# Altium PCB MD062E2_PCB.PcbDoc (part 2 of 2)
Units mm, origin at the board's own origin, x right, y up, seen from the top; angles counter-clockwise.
Board outline 85.34 x 64.01 mm, 4 copper layers (Top Layer, Signal Layer 1, Signal Layer 2, Bottom Layer), stack 1.565 mm thick; 172 components, 94 nets, 455 pads, 231 vias.
Unrouted connection lines stored in the file: 2.
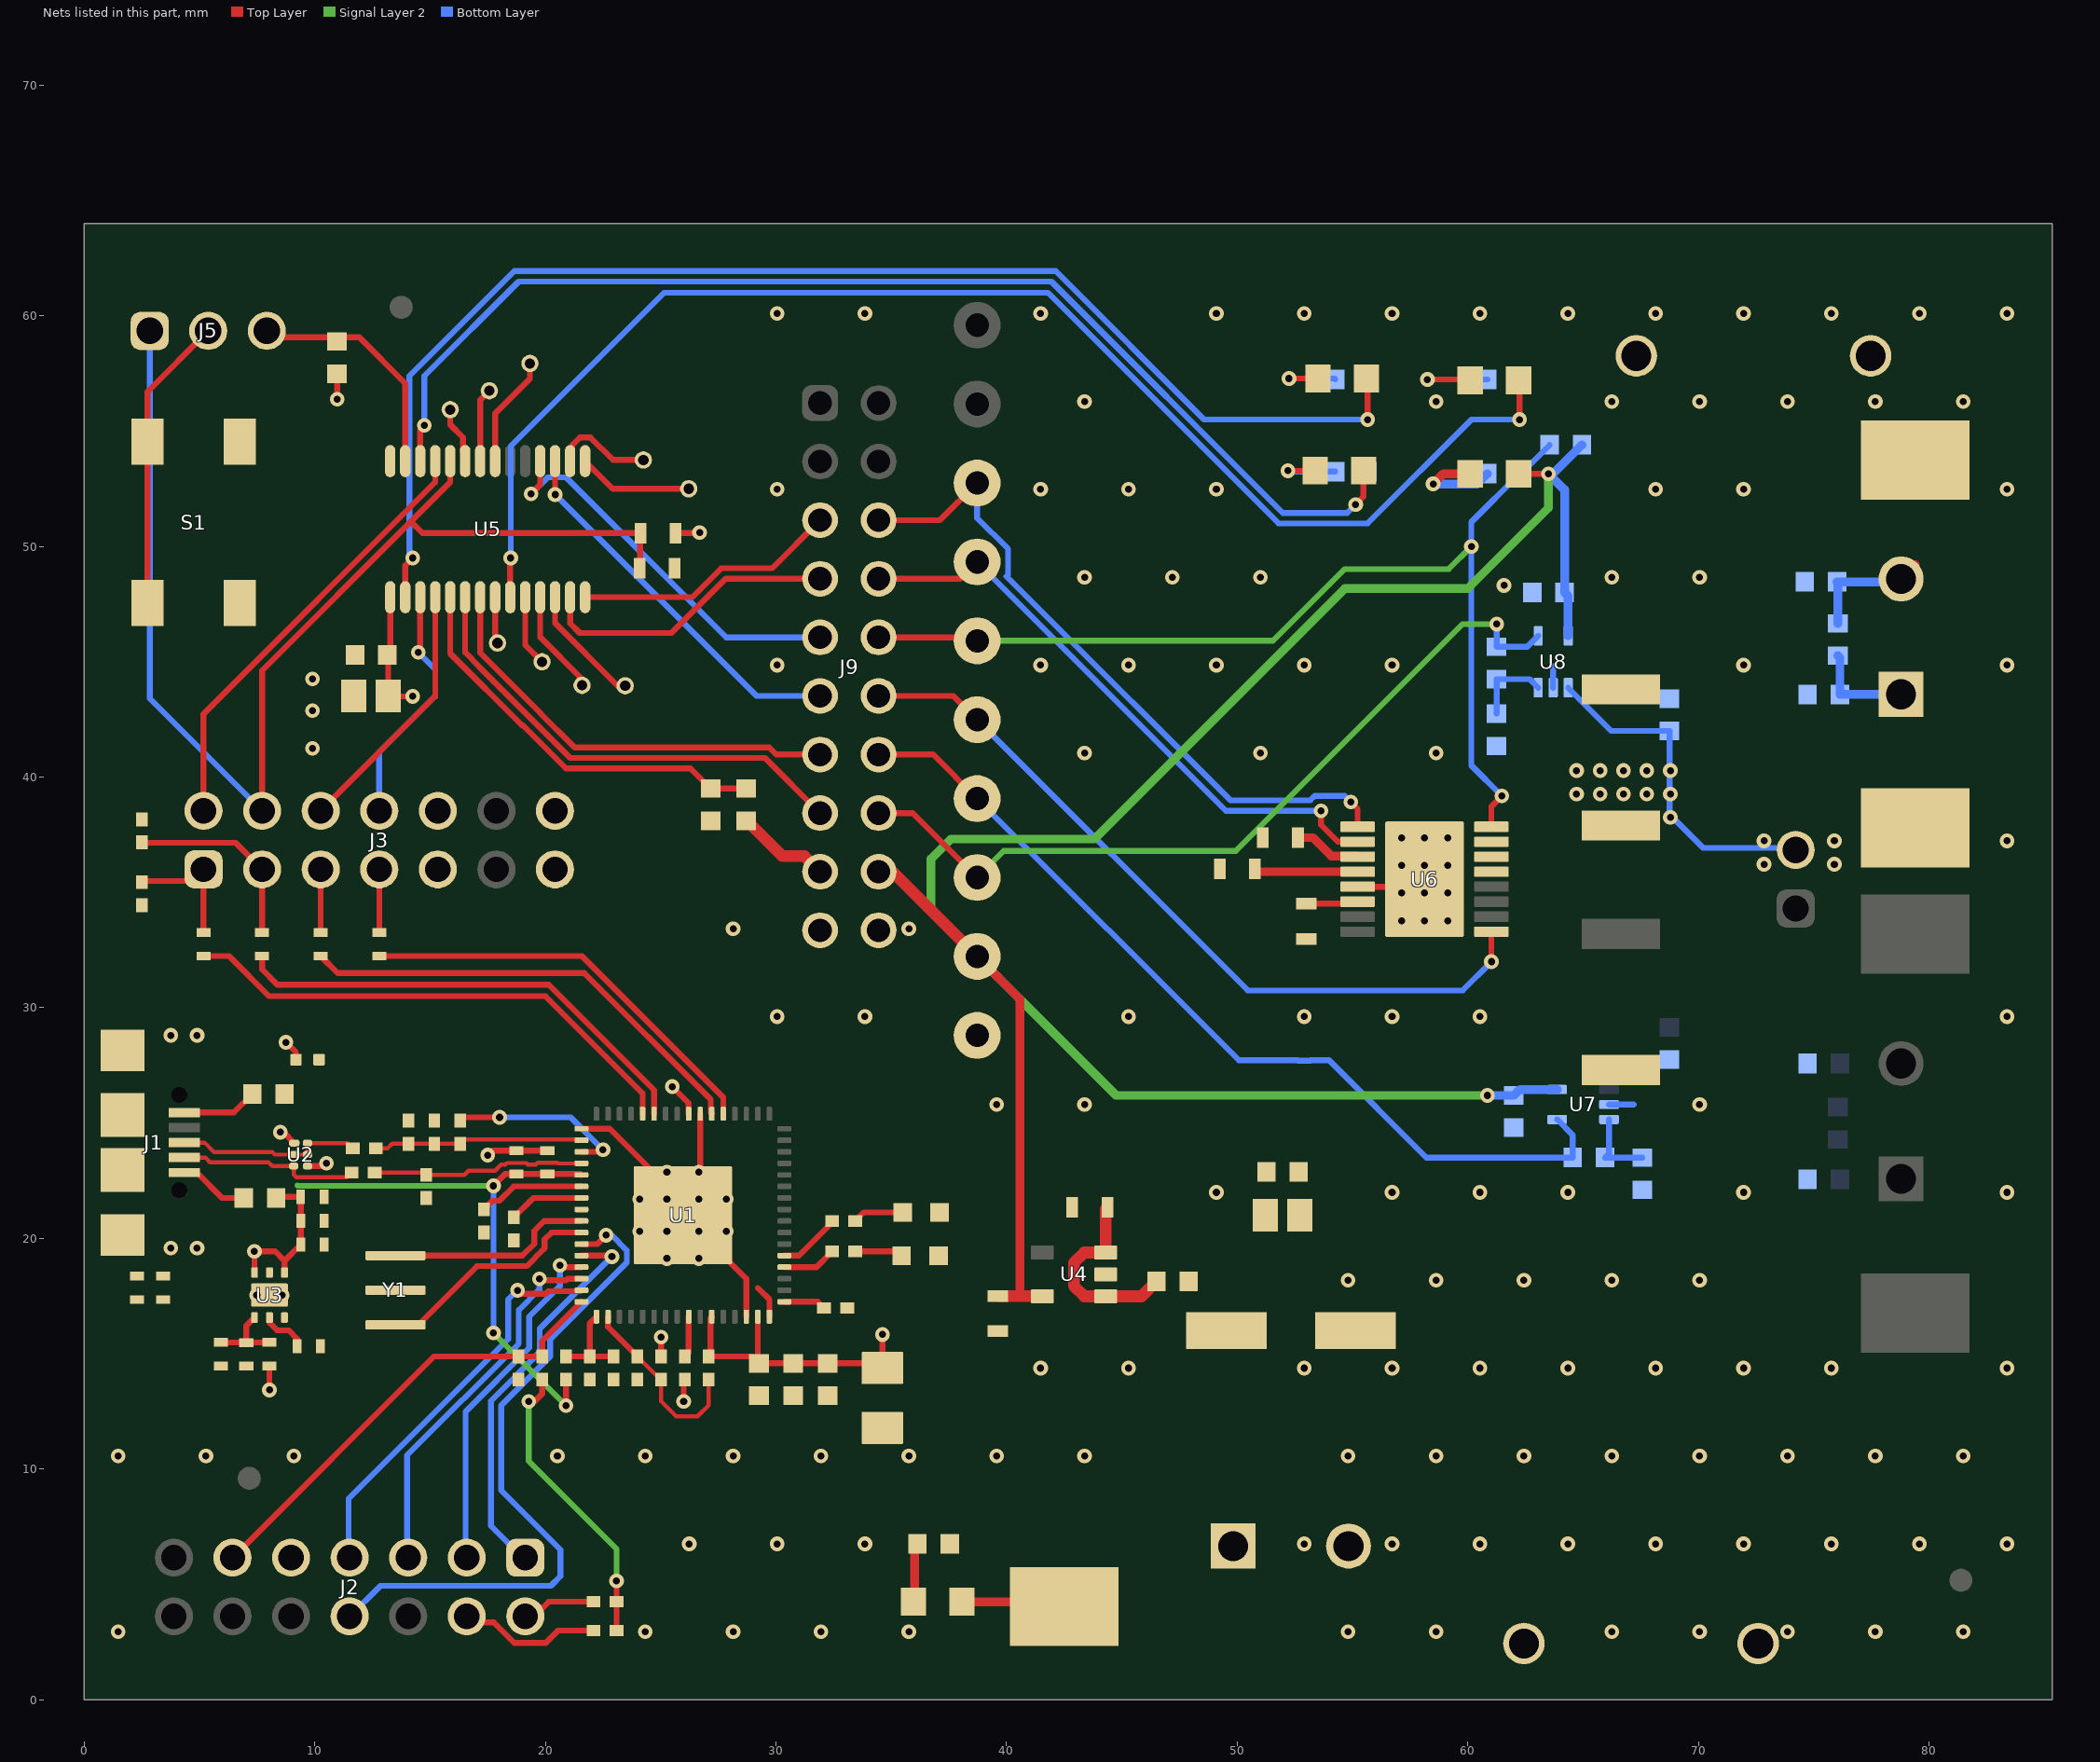
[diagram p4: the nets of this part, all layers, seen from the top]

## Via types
v1: diameter 0.635/0.635/0.635/0.635 (per signal layer), hole 0.305, Top Layer to Bottom Layer, tented both sides, 231 vias

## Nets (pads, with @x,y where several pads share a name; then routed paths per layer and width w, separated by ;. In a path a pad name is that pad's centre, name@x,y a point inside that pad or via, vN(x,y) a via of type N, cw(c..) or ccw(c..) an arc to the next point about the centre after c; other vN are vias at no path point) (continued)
BIN1: J9.6 TP19.1 U6.9 | length 29.9
  Top Layer w0.254: J9.6@34.452,51.139 37.112,51.139 TP19.1@38.725,52.752 ; v1(54.929,38.92) 55.224,38.625 U6.9@55.224,37.849
  Bottom Layer w0.254: TP19.1@38.725,52.752 38.725,51.23 40.068,49.887 40.068,48.774 39.996,48.702 41.127,47.571 49.704,38.994 53.173,38.994 53.363,39.185 54.664,39.185 v1(54.929,38.92)
BIN1_MCU: J9.5 U5.14 | length 11.6
  Top Layer w0.254: U5.14@21.725,47.8 26.378,47.8 27.631,49.053 29.826,49.053 J9.5@31.912,51.139
BIN2: J9.8 TP20.1 U6.10 | length 26.5
  Top Layer w0.254: J9.8@34.452,48.599 37.993,48.599 TP20.1@38.725,49.331 ; v1(53.63,38.54) 53.63,37.934 54.365,37.199 U6.10@55.224,37.199
  Bottom Layer w0.254: TP20.1@38.725,49.331 49.516,38.54 v1(53.63,38.54)
BIN2_MCU: J9.7 U5.13 | length 13.1
  Top Layer w0.254: U5.13@21.075,47.8 21.075,46.665 21.494,46.246 25.466,46.246 27.819,48.599 J9.7@31.912,48.599
BISEN: C35.1 J7.2 R24.2 U6.6 U8.1 | length 14.9
  Bottom Layer w0.254: U8.1@64.353,43.875 66.228,42 C35.1@68.75,42 68.75,38.387 70.206,36.932 J7.2@74.219,36.932
  other v1: 72.847,36.22 75.895,36.22 72.847,37.236 75.895,37.236 68.783,38.252 64.719,39.268 65.735,39.268 66.751,39.268 67.767,39.268 68.783,39.268 64.719,40.284 65.735,40.284 66.751,40.284 67.767,40.284 68.783,40.284
BOUT1: C38.2 C39.1 J11.2 TP16.1 U6.7 | length 6.9
  Top Layer w0.381: J11.2@78.791,48.592 J11.2@79.4,49.201 ; TP16.1@79.4,52.327 TP16.1@79.4,53.75
  Bottom Layer w0.381: C38.2@76.048,46.663 76.048,48.43 C39.1@76.014,48.463 78.662,48.463 J11.2@78.791,48.592
BOUT2: C38.1 C41.1 J11.1 TP15.1 U6.5 | length 5.8
  Top Layer w0.381: TP15.1@79.4,37.795 TP15.1@79.4,39.218
  Bottom Layer w0.381: C38.1@76.048,45.263 76.138,45.172 C41.1@76.138,43.586 78.785,43.586 J11.1@78.791,43.592
DEV_ID: R21.1 R22.2 U5.5 | length 17.7
  Top Layer w0.254: U5.5@15.875,47.8 15.875,45.36 19.005,42.23 19.041,42.23 20.895,40.376 26.296,40.376 R22.2@27.164,39.509 R21.1@28.717,39.509
EZFET_AVBUS: C18.1 R14.1 R15.2 U1.1 | length 3.9
  Top Layer w0.254: R14.1@20.9,14.885 C18.1@21.931,14.885 ; U1.1@22.217,16.605 21.931,16.319 C18.1@21.931,14.885 ; R15.2@22.962,14.885 C18.1@21.931,14.885
EZFET_AVCC2ADC: C19.1 R16.1 R17.2 U1.2 | length 8.3
  Top Layer w0.178: C19.1@23.994,14.885 24.994,13.885 R17.2@25.025,13.885 25.025,12.931 25.672,12.285 26.596,12.285 27.087,12.776 R16.1@27.087,13.885
  Top Layer w0.254: U1.2@22.717,16.605 22.717,16.162 C19.1@23.994,14.885
EZFET_D_N: C11.1 R4.2 U1.52 | length 9.3
  Top Layer w0.178: R4.2@12.6,22.86 14.732,22.86 C11.1@14.837,22.755 16.492,22.755 16.677,22.94 17.822,22.94 18.088,23.206 18.262,23.206 18.326,23.27 19.174,23.27 19.238,23.206 19.593,23.206 19.663,23.276 20.512,23.276 20.538,23.25 21.562,23.25 U1.52@21.567,23.255
EZFET_D_P: C12.1 R5.2 R6.2 R7.1 U1.50 | length 9.1
  Top Layer w0.178: R5.2@12.65,23.9 13.15,23.9 13.355,24.105 R6.2@14.062,24.105 C12.1@15.187,24.105 R7.1@16.312,24.105 16.462,24.255 16.462,24.292 21.529,24.292 U1.50@21.567,24.255
EZFET_LED0: R1.2 U1.20 | length 2.4
  Top Layer w0.254: U1.20@30.367,18.755 31.757,18.755 R1.2@32.437,19.435
EZFET_LED1: R2.2 U1.21 | length 2.7
  Top Layer w0.254: U1.21@30.367,19.255 31,19.255 32.437,20.692 R2.2@32.437,20.75
EZFET_PUR: R7.2 U1.51 | length 7.8
  Top Layer w0.254: R7.2@16.312,25.105 16.458,25.25 v1(18.017,25.25) ; U1.51@21.567,23.755 22.406,23.755 v1(22.5,23.848)
  Bottom Layer w0.254: v1(18.017,25.25) 21.098,25.25 v1(22.5,23.848)
EZFET_RST: C24.1 J2.11 R19.1 U1.64 | length 20.2
  Top Layer w0.254: J2.11@6.385,6.09 15.18,14.885 C24.1@18.837,14.885 R19.1@19.869,14.885 19.869,15.557 U1.64@21.567,17.255
EZFET_TCK: J2.7 U1.63 | length 17.6
  Top Layer w0.254: v1(18.793,17.75) 18.937,17.605 20.017,17.605 20.12,17.709 21.521,17.709 U1.63@21.567,17.755
  Bottom Layer w0.254: J2.7@11.465,6.09 11.465,8.703 18.394,15.633 18.394,17.352 v1(18.793,17.75)
EZFET_TDI: J2.3 U1.61 | length 15.4
  Top Layer w0.254: v1(20.634,18.834) 20.713,18.755 U1.61@21.567,18.755
  Bottom Layer w0.254: J2.3@16.545,6.09 16.545,12.499 19.302,15.257 19.302,16.605 20.634,17.936 v1(20.634,18.834)
EZFET_TDO: J2.1 U1.60 | length 17.2
  Top Layer w0.254: U1.60@21.567,19.255 22.843,19.255 v1(22.887,19.211)
  Bottom Layer w0.254: J2.1@19.085,6.09 17.637,7.537 17.637,12.95 19.756,15.069 19.756,16.08 v1(22.887,19.211)
EZFET_TEST: J2.8 U1.59 | length 29.8
  Top Layer w0.254: U1.59@21.567,19.755 22.255,19.755 v1(22.639,20.139)
  Bottom Layer w0.254: J2.8@11.465,3.55 12.853,4.938 20.239,4.938 20.653,5.352 20.653,6.51 18.093,9.07 18.091,9.07 18.091,12.762 20.21,14.881 20.21,15.622 23.532,18.944 23.532,19.478 22.871,20.139 v1(22.639,20.139)
EZFET_TMS: J2.5 U1.62 | length 16.4
  Top Layer w0.254: v1(19.75,18.25) 19.81,18.189 20.901,18.189 20.961,18.25 21.562,18.25 U1.62@21.567,18.255
  Bottom Layer w0.254: J2.5@14.005,6.09 14.005,10.601 18.848,15.445 18.848,16.894 19.75,17.796 v1(19.75,18.25)
EZFET_UARTRXD: R10.1 U1.38 | length 20.1
  Top Layer w0.254: R10.1@10.258,32.242 11,31.5 21.692,31.5 27.171,26.021 27.171,25.451 U1.38@27.217,25.405
EZFET_UARTTXD: R11.1 U1.37 | length 18.2
  Top Layer w0.254: R11.1@12.803,32.242 21.592,32.242 27.717,26.117 U1.37@27.717,25.405
EZFET_USB_Shield: C5.1 J1.Shell R3.2
  other v1: 3.758,19.581 4.898,19.581 3.758,28.804 4.898,28.804
EZFET_V18: C2.1 U1.55 | length 3.3
  Top Layer w0.254: C2.1@18.637,20.913 19.479,21.755 U1.55@21.567,21.755
EZFET_VBUS: C9.2 C13.1 C14.1 C15.1 C23.1 C25.1 L1.2 R14.2 U1.53 U2.1 U3.4 U3.6 | length 33.3
  Top Layer w0.254: U3.6@7.387,18.52 7.387,19.431 v1(7.384,19.435) 8.279,19.435 8.687,19.027 ; L1.2@8.328,21.755 8.377,21.803 C13.1@9.387,21.803 9.395,21.795 C14.1@9.395,20.763 C15.1@9.395,19.735 8.687,19.027 ; v1(8.503,24.605) 8.642,24.605 U2.1@9.112,24.135 ; U3.4@8.687,18.52 8.687,19.027 ; v1(8.75,28.5) 9.187,28.063 C9.2@9.187,27.75 ; v1(17.75,22.28) 18.261,22.79 C25.1@18.75,22.79 20.081,22.79 C23.1@20.087,22.797 21.525,22.797 U1.53@21.567,22.755 ; v1(20.9,12.75) R14.2@20.9,13.885
  Signal Layer 2 w0.254: 9.25,22.3 9.271,22.28 v1(17.75,22.28) ; v1(17.75,15.9) v1(20.9,12.75)
  Bottom Layer w0.254: v1(17.75,15.9) v1(17.75,22.28)
EZFET_VCC: C6.1 C7.1 C8.1 C10.1 J3.9 R12.1 R13.1 R16.2 R18.2 R19.2 U1.11 U1.15 U1.40 | length 28.3
  Top Layer w0.254: v1(8.037,13.429) R18.2@8.037,14.477 ; v1(19.275,12.931) 19.533,12.931 19.869,13.267 R19.2@19.869,13.885 ; R12.1@23.087,3 R13.1@23.087,4.25 v1(23.087,5.148) ; v1(25.5,26.58) 26.217,25.863 U1.40@26.217,25.405 ; U1.11@27.217,16.605 27.164,16.552 27.164,14.961 R16.2@27.087,14.885 28.963,14.885 C7.1@29.217,14.631 ; U1.15@29.217,16.605 C7.1@29.217,14.631 ; v1(34.613,15.835) C6.1@34.613,14.385 34.413,14.585 C10.1@32.237,14.585 C8.1@30.75,14.585 C7.1@29.263,14.585 C7.1@29.217,14.631
  Signal Layer 2 w0.254: v1(19.275,12.931) 19.275,10.352 23.087,6.539 v1(23.087,5.148)
EZFET_VCORE: C3.1 U1.17 | length 1.8
  Top Layer w0.254: U1.17@30.367,17.255 31.817,17.255 C3.1@32.087,16.985
EZFET_VREF: C1.1 U1.9 | length 1.8
  Top Layer w0.254: C1.1@26.056,14.885 26.217,15.045 U1.9@26.217,16.605
EZFET_VUSB: C4.1 U1.54 | length 4.6
  Top Layer w0.254: C4.1@17.337,21.26 17.713,21.635 18.017,21.635 18.636,22.255 U1.54@21.567,22.255
EZFET_XT2IN: U1.57 Y1.1 | length 9
  Top Layer w0.254: Y1.1@13.5,19.255 19.005,19.255 19.519,19.769 19.519,20.33 19.944,20.755 U1.57@21.567,20.755
EZFET_XT2OUT: U1.58 Y1.3 | length 9.9
  Top Layer w0.254: Y1.3@13.5,16.255 14.491,16.255 17.037,18.801 19.193,18.801 19.906,19.513 ; 19.944,19.552 19.973,19.581 19.973,19.964 20.264,20.255 U1.58@21.567,20.255
GND: C1.2 C2.2 C3.2 C4.2 C5.2 C6.2 C7.2 C8.2 C9.1 C10.2 C11.2 C12.2 C13.2 C14.2 C15.2 C16.1 C17.1 C18.2 C19.2 C20.2 C21.2 C22.2 C23.2 C24.2 C25.2 C26.2 C27.2 C28.2 C29.2 C30.2 C31.2 C32.2 C33.2 C34.2 C35.2 C37.2 C39.2 C40.2 C41.2 C42.2 C43.2 C44.2 C46.2 D1.1 D2.1 J2.9 J3.13 J3.14 J4.2 J9.19 J9.20 L2.2 R3.1 R6.1 R15.1 R17.1 R22.1 R23.1 R24.1 R26.1 R27.1 R28.1 R29.1 R32.1 R33.1 S1.3 S1.4 TP7.1 TP7.2 TP8.1 TP8.2 TP26.1 U1.14 U1.16 U1.39 U1.49 U1.56 U1.65 U2.4 U3.3 U3.5 U3.7@8.037,17.545 U4.2 U5.28 U6.13 U6.17 U7.2 U8.2 Y1.2 | length 28.4
  Top Layer w0.254: U2.4@9.687,23.135 10.389,23.135 v1(10.509,23.255) ; v1(17.5,23.61) 17.697,23.806 C25.2@18.75,23.806 20.081,23.806 C23.2@20.087,23.813 ; U1.49@21.567,24.755 22.794,24.755 25.967,21.582 U1.65@25.967,21.005 ; R17.1@25.025,14.885 v1(25.025,15.718) ; v1(26,12.931) 26,13.828 C1.2@26.056,13.885 ; U1.39@26.717,25.405 26.717,21.755 v1(26.662,21.7) U1.65@25.967,21.005 ; U1.14@28.717,16.605 28.717,18.255 v1(26.662,20.31) U1.65@25.967,21.005 ; 29.217,17.851 29.717,17.351 U1.16@29.717,16.605 ; U6.13@55.224,35.249 57.799,35.249 U6.17@58.124,35.574
  Bottom Layer w0.254: U8.2@63.703,43.875 63.703,44.806 ; U7.2@66.125,25.806 67.2,25.806
  other v1: 1.473,2.946 24.333,2.946 28.143,2.946 31.953,2.946 35.763,2.946 54.813,2.946 58.623,2.946 66.243,2.946 70.053,2.946 73.863,2.946 77.673,2.946 81.483,2.946 26.238,6.756 30.048,6.756 33.858,6.756 52.908,6.756 56.718,6.756 60.528,6.756 64.338,6.756 68.148,6.756 71.958,6.756 75.768,6.756 79.578,6.756 83.388,6.756 1.473,10.566 5.283,10.566 9.093,10.566 20.523,10.566 24.333,10.566 28.143,10.566 31.953,10.566 35.763,10.566 39.573,10.566 43.383,10.566 54.813,10.566 58.623,10.566 62.433,10.566 66.243,10.566 70.053,10.566 73.863,10.566 77.673,10.566 81.483,10.566 41.478,14.376 45.288,14.376 52.908,14.376 56.718,14.376 60.528,14.376 64.338,14.376 68.148,14.376 71.958,14.376 75.768,14.376 83.388,14.376 7.487,17.545 8.587,17.545 54.813,18.186 58.623,18.186 62.433,18.186 66.243,18.186 70.053,18.186 25.272,19.13 26.662,19.13 24.092,20.31 25.272,20.31 27.842,20.31 24.092,21.7 25.272,21.7 27.842,21.7 49.098,21.996 56.718,21.996 60.528,21.996 64.338,21.996 71.958,21.996 83.388,21.996 25.272,22.88 26.662,22.88 39.573,25.806 43.383,25.806 70.053,25.806 30.048,29.616 33.858,29.616 45.288,29.616 52.908,29.616 56.718,29.616 60.528,29.616 83.388,29.616 28.143,33.426 35.763,33.426 57.124,33.774 58.124,33.774 59.124,33.774 57.124,34.974 58.124,34.974 59.124,34.974 57.124,36.174 58.124,36.174 59.124,36.174 83.388,37.236 57.124,37.374 58.124,37.374 59.124,37.374 43.383,41.046 51.003,41.046 58.623,41.046 9.899,41.25 9.899,42.887 9.899,44.258 30.048,44.856 41.478,44.856 45.288,44.856 49.098,44.856 52.908,44.856 56.718,44.856 71.958,44.856 83.388,44.856 61.57,48.311 43.383,48.666 47.193,48.666 51.003,48.666 66.243,48.666 70.053,48.666 30.048,52.476 41.478,52.476 45.288,52.476 49.098,52.476 68.148,52.476 71.958,52.476 83.388,52.476 43.383,56.286 58.623,56.286 66.243,56.286 70.053,56.286 73.863,56.286 77.673,56.286 81.483,56.286 30.048,60.096 33.858,60.096 41.478,60.096 49.098,60.096 52.908,60.096 56.718,60.096 60.528,60.096 64.338,60.096 68.148,60.096 71.958,60.096 75.768,60.096 79.578,60.096 83.388,60.096
GUI_STATUS: D5.2 U5.9 | length 60.8
  Top Layer w0.254: U5.9@18.475,47.8 18.475,49.475 v1(18.5,49.5) ; D5.2@62.2,57.201 62.25,57.151 v1(62.25,55.5)
  Bottom Layer w0.254: v1(18.5,49.5) 18.5,54.346 25.157,61.003 41.786,61.003 51.789,51 55.654,51 60.154,55.5 v1(62.25,55.5)
MCU_STATUS: D4.2 U5.2 | length 57.7
  Top Layer w0.254: U5.2@13.925,47.8 13.925,49.175 v1(14.25,49.5) ; D4.2@55.604,57.281 55.654,57.231 v1(55.654,55.5)
  Bottom Layer w0.254: v1(14.25,49.5) 14.106,49.644 14.106,57.395 18.649,61.938 42.134,61.938 48.573,55.5 v1(55.654,55.5)
MCU_UARTRXD: J3.8 U5.3 | length 10.6
  Top Layer w0.254: v1(14.487,45.414) 14.575,45.501 U5.3@14.575,47.8
  Bottom Layer w0.254: J3.8@12.798,38.54 12.798,41.08 15.225,43.507 15.225,44.676 v1(14.487,45.414)
MCU_UARTTXD: J3.6 U5.4 | length 11.3
  Top Layer w0.254: J3.6@10.258,38.54 15.225,43.507 U5.4@15.225,47.8
NetC16_2: C16.2 J3.1 R8.2 | length 5.5
  Top Layer w0.254: C16.2@2.625,35.5 4.678,35.5 J3.1@5.178,36 R8.2@5.178,33.258
NetC17_2: C17.2 J3.3 R9.2 | length 8.5
  Top Layer w0.254: C17.2@2.625,37 2.625,37.152 6.566,37.152 J3.3@7.718,36 R9.2@7.718,33.258
NetC20_1: C20.1 U3.2 | length 2
  Top Layer w0.254: U3.2@8.037,16.57 8.037,16.341 8.361,16.018 8.867,16.018 9.237,15.648 C20.1@9.237,15.327
NetC21_1: C21.1 C22.1 R18.1 U3.1 | length 3.3
  Top Layer w0.254: C22.1@5.937,15.493 C21.1@7.034,15.493 ; C21.1@7.034,15.485 C21.1@7.034,15.493 ; U3.1@7.387,16.57 7.034,16.216 C21.1@7.034,15.493 ; R18.1@8.037,15.493 C21.1@7.034,15.493
NetC26_1: C26.1 R20.1 U4.1 U4.3 | length 8.6
  Top Layer w0.381: C26.1@44.297,21.269 C26.1@44.373,21.345
  Top Layer w0.508: C26.1@44.297,21.269 U4.3@44.297,19.39 43.372,19.39 42.922,18.94 42.922,17.94 43.372,17.49 U4.1@44.297,17.49 45.855,17.49 R20.1@46.5,18.136
NetC44_1: C44.1 U6.14 | length 2.3
  Top Layer w0.254: C44.1@53,34.512 55.137,34.512 U6.14@55.224,34.599
NetC45_1: C45.1 U6.11 | length 3
  Top Layer w0.381: C45.1@52.574,37.374 53.293,37.374 54.083,36.583 55.189,36.583 U6.11@55.224,36.549
NetD1_2: D1.2 R1.1 | length 2.1
  Top Layer w0.254: R1.1@33.437,19.435 35.265,19.435 D1.2@35.45,19.25
NetD2_2: D2.2 R2.1 | length 2.2
  Top Layer w0.254: R2.1@33.437,20.75 33.817,21.13 D2.2@35.5,21.13
NetD4_1: D4.1 R26.2 | length 3.3
  Top Layer w0.254: v1(52.25,57.281) D4.1@53.504,57.281
  Bottom Layer w0.254: v1(52.25,57.281) 54.218,57.281 R26.2@54.254,57.245
NetD5_1: D5.1 R29.2 | length 4.5
  Top Layer w0.254: v1(58.25,57.24) 60.061,57.24 D5.1@60.1,57.201
  Bottom Layer w0.254: v1(58.25,57.24) R29.2@60.85,57.24
NetD6_1: D6.1 R32.2 | length 3.3
  Top Layer w0.254: v1(52.199,53.284) D6.1@53.379,53.284
  Bottom Layer w0.254: v1(52.199,53.284) 52.235,53.248 R32.2@54.254,53.248
NetD7_1: D7.1 R33.2 | length 2.4
  Top Layer w0.381: D7.1@36.012,4.455 36.012,6.63 R33.2@36.137,6.755
NetD8_1: D8.1 R35.2 | length 4.3
  Top Layer w0.381: v1(58.5,52.712) 58.942,53.154 D8.1@60.1,53.154
  Bottom Layer w0.381: v1(58.5,52.712) 60.408,52.712 R35.2@60.85,53.154
NetJ1_1: J1.1 L1.1 | length 3
  Top Layer w0.254: J1.1@4.351,22.856 4.886,22.856 5.988,21.755 L1.1@6.928,21.755
NetJ1_5: J1.5 L2.1 | length 3.3
  Top Layer w0.254: J1.5@4.351,25.456 6.494,25.456 L2.1@7.292,26.255
NetJ2_2: J2.2 R13.2 | length 3.2
  Top Layer w0.254: J2.2@19.133,3.619 19.511,3.619 20.142,4.25 R13.2@22.087,4.25
NetJ2_4: J2.4 R12.2 | length 6.2
  Top Layer w0.254: J2.4@16.593,3.619 16.86,3.352 17.771,3.352 18.656,2.467 20.019,2.467 20.552,3 R12.2@22.087,3
NetJ3_5: J3.5 R10.2 | length 2.7
  Top Layer w0.254: R10.2@10.258,33.258 J3.5@10.258,36
NetJ3_7: J3.7 R11.2 | length 2.7
  Top Layer w0.254: J3.7@12.798,36 12.803,35.995 R11.2@12.803,33.258
NetJ5_2: J5.2 S1.1 S1.2 | length 12.9
  Top Layer w0.254: S1.1@2.75,47.55 S1.2@2.75,54.55 2.75,54.633 2.743,54.64 2.743,56.704 J5.2@5.385,59.345
NetP1.6_1: P1.6.1 U5.22 | length 3.2
  Top Layer w0.254: U5.22@17.175,53.7 17.175,56.353 P1.6.1@17.572,56.75
NetP1.7_1: P1.7.1 U5.23 | length 2.5
  Top Layer w0.254: P1.7.1@15.875,55.929 15.875,55.279 16.427,54.727 16.427,54.092 16.525,53.994 U5.23@16.525,53.7
NetP2.0_1: P2.0.1 U5.10 | length 3.1
  Top Layer w0.254: U5.10@19.125,47.8 19.125,45.732 P2.0.1@19.857,45
NetP2.1_1: P2.1.1 U5.11 | length 4.6
  Top Layer w0.254: U5.11@19.775,47.8 19.775,46.075 21.592,44.258 P2.1.1@21.592,43.981
NetP2.2_1: P2.2.1 U5.12 | length 5.3
  Top Layer w0.254: U5.12@20.425,47.8 20.425,46.673 23.14,43.958 P2.2.1@23.461,43.958
NetP2.3_1: P2.3.1 U5.16 | length 4.4
  Top Layer w0.254: U5.16@21.075,53.7 21.125,53.75 21.173,53.75 21.173,54.404 21.496,54.727 21.954,54.727 22.931,53.75 P2.3.1@24.25,53.75
NetP3.1_1: P3.1.1 U5.8 | length 2
  Top Layer w0.254: U5.8@17.825,47.8 17.825,45.914 P3.1.1@17.925,45.814
NetP3.4_1: P3.4.1 U5.15 | length 5
  Top Layer w0.254: U5.15@21.725,53.7 22.925,52.5 P3.4.1@26.217,52.5
NetP3.7_1: P3.7.1 U5.21 | length 4.9
  Top Layer w0.254: U5.21@17.825,53.7 17.825,55.766 19.332,57.273 P3.7.1@19.332,57.935
NetR27_2: R27.2 R30.1 U7.3 | length 3.3
  Bottom Layer w0.254: U7.3@66.125,25.156 66.125,23.681 R30.1@65.95,23.506 65.956,23.5 66.75,23.5 66.756,23.506 R27.2@67.57,23.506
NetR28_2: R28.2 R31.1 U8.3 | length 3.5
  Bottom Layer w0.254: R28.2@61.25,42.75 R31.1@61.25,44.25 62.678,44.25 U8.3@63.053,43.875
nFAULT: J9.10 R34.1 R35.1 TP21.1 U6.8 | length 46.2
  Top Layer w0.254: J9.10@34.452,46.059 38.576,46.059 TP21.1@38.725,45.909 ; U6.8@61.024,37.849 61.024,38.73 v1(61.479,39.185)
  Signal Layer 2 w0.254: TP21.1@38.725,45.909 51.555,45.909 54.664,49.019 59.173,49.019 v1(60.154,50)
  Bottom Layer w0.254: v1(61.479,39.185) 60.154,40.509 60.154,51.058 R35.1@62.25,53.154 62.298,53.154 R34.1@63.551,54.407
nFAULT_MCU: J9.9 U5.18 | length 17.3
  Top Layer w0.254: v1(19.377,52.274) 19.775,52.672 U5.18@19.775,53.7
  Bottom Layer w0.254: v1(19.377,52.274) 20.098,52.995 20.905,52.995 27.841,46.059 J9.9@31.912,46.059
nSLEEP: J9.12 TP22.1 U6.1 | length 33.7
  Top Layer w0.254: J9.12@34.452,43.519 37.694,43.519 TP22.1@38.725,42.488 ; v1(61.024,32) U6.1@61.024,33.299
  Bottom Layer w0.254: TP22.1@38.725,42.488 50.463,30.75 59.774,30.75 v1(61.024,32)
nSLEEP_MCU: J9.11 U5.17 | length 16.6
  Top Layer w0.254: v1(20.425,52.25) U5.17@20.425,53.7
  Bottom Layer w0.254: v1(20.425,52.25) 29.156,43.519 J9.11@31.912,43.519
PUSH: J5.3 R36.1 U5.27 | length 10.3
  Top Layer w0.254: J5.3@7.925,59.345 8.203,59.067 10.973,59.067 11.933,59.067 13.925,57.074 U5.27@13.925,53.7
RST/SBWTDIO: C46.1 J3.4 J5.1 R25.1 U5.24 | length 53.1
  Top Layer w0.254: J3.4@7.718,38.54 7.718,44.628 14.167,51.077 ; U5.24@15.875,53.7 15.875,52.785 14.167,51.077 ; C46.1@24.088,49.05 24.108,49.069 24.108,50.557 R25.1@24.128,50.577 14.667,50.577 14.167,51.077
  Bottom Layer w0.254: J5.1@2.845,59.345 2.845,43.413 J3.4@7.718,38.54
STALL: D6.2 U5.26 | length 51.8
  Top Layer w0.254: U5.26@14.575,53.7 14.575,55.075 v1(14.75,55.25) ; v1(55.14,51.82) 55.479,52.159 D6.2@55.479,53.284
  Bottom Layer w0.254: v1(14.75,55.25) 14.75,57.388 18.846,61.484 41.946,61.484 51.977,51.454 54.774,51.454 v1(55.14,51.82)
T_RST_RST: R9.1 U1.43 | length 20.8
  Top Layer w0.254: R9.1@7.718,32.242 7.718,31.658 8.377,31 20.154,31 24.717,26.437 U1.43@24.717,25.405
T_TEST_TCKC: R8.1 U1.44 | length 22.4
  Top Layer w0.254: R8.1@5.178,32.242 6.286,32.242 8.028,30.5 20.012,30.5 24.217,26.295 U1.44@24.217,25.405
TST/SBWTCK: J3.2 U5.25 | length 19.3
  Top Layer w0.254: J3.2@5.178,38.54 5.178,42.73 15.225,52.777 U5.25@15.225,53.7
USB_D_N: J1.2 R4.1 U2.3 | length 7.9
  Top Layer w0.178: J1.2@4.351,23.506 5.26,23.506 5.462,23.305 7.992,23.305 8.162,23.135 U2.3@9.087,23.135 9.087,22.763 9.195,22.655 9.198,22.658 9.754,22.658 9.763,22.648 10.76,22.648 10.769,22.658 11.398,22.658 R4.1@11.6,22.86
USB_D_P: J1.3 R5.1 U2.2 U2.5 U2.6 | length 8.1
  Top Layer w0.178: J1.3@4.351,24.156 5.221,24.156 5.641,23.736 8.171,23.736 8.273,23.635 U2.2@9.087,23.635 U2.5@9.687,23.635 U2.6@9.687,24.135 11.415,24.135 R5.1@11.65,23.9
VCC: C27.1 C28.1 C32.1 C42.1 C43.1 D8.2 J3.10 J9.17 J9.18 R21.2 R25.2 R34.2 R36.2 TP25.1 U4.5 U5.1 U7.5 U8.5 | length 112.9
  Top Layer w0.254: v1(10.973,56.38) R36.2@10.973,57.485 ; U5.1@13.275,47.8 13.275,45.414 C28.1@13.15,45.289 13.187,45.251 C27.1@13.187,43.519 13.206,43.5 v1(14.25,43.5) ; R25.2@25.652,50.577 26.666,50.577 v1(26.689,50.599) ; D8.2@62.2,53.154 v1(63.5,53.154)
  Top Layer w0.381: TP25.1@38.725,32.225 40.577,30.373 40.577,17.507
  Top Layer w0.508: R21.2@28.717,38.109 28.742,38.109 30.281,36.569 31.242,36.569 J9.17@31.912,35.899 ; J9.18@34.452,35.899 35.051,35.899 TP25.1@38.725,32.225 ; C32.1@39.623,17.507 40.577,17.507 41.53,17.507 U4.5@41.547,17.49
  Signal Layer 2 w0.381: v1(60.85,26.2) 44.75,26.2 TP25.1@38.725,32.225 36.728,34.222 36.728,36.456 37.588,37.315 43.815,37.315 54.674,48.174 60,48.174 63.5,51.674 v1(63.5,53.154)
  Bottom Layer w0.381: v1(60.85,26.2) C42.1@62,26.2 62.256,26.456 U7.5@63.875,26.456 ; U8.5@64.353,46.125 64.353,47.847 C43.1@64.2,48 64.2,52.454 v1(63.5,53.154) 63.698,53.154 R34.2@64.951,54.407
VM: C29.1 C30.1 C31.1 C33.1 C45.2 D7.2 J4.1 R20.2 TP1.1 U6.12 | length 9.1
  Top Layer w0.381: D7.2@38.062,4.25 42.293,4.25 TP1.1@42.5,4.043 ; C33.1@50.774,36.016 50.891,35.899 U6.12@55.224,35.899 ; C45.2@51.174,37.299 C45.2@51.174,37.374
VSENSE_A: J9.14 R30.2 TP23.1 U7.4 | length 39.3
  Top Layer w0.254: J9.14@34.452,40.979 36.813,40.979 TP23.1@38.725,39.067
  Bottom Layer w0.254: TP23.1@38.725,39.067 50.071,27.721 52.622,27.721 52.641,27.702 53.175,27.702 53.194,27.721 53.99,27.721 58.205,23.506 R30.2@64.55,23.506 64.55,24.481 U7.4@63.875,25.156
VSENSE_A_MCU: J9.13 U5.7 | length 19
  Top Layer w0.254: U5.7@17.175,47.8 17.175,45.395 19.787,42.783 19.787,42.767 21.271,41.284 29.709,41.284 30.015,40.979 J9.13@31.912,40.979
VSENSE_B: J9.16 R31.2 TP24.1 U8.4 | length 35.5
  Top Layer w0.254: J9.16@34.452,38.439 35.932,38.439 TP24.1@38.725,35.646
  Signal Layer 2 w0.254: TP24.1@38.725,35.646 39.876,36.798 49.945,36.798 59.782,46.634 v1(61.25,46.634)
  Bottom Layer w0.254: v1(61.25,46.634) R31.2@61.25,45.65 62.578,45.65 U8.4@63.053,46.125
VSENSE_B_MCU: J9.15 U5.6 | length 20.7
  Top Layer w0.254: U5.6@16.525,47.8 16.525,45.403 17.142,44.786 17.142,44.77 21.083,40.83 29.521,40.83 J9.15@31.912,38.439
pads on no net: FID1.1 FID2.1 FID3.1 H1.0 H2.0 H3.0 H4.0 J1.4 J1.MH1 J1.MH2 J2.6 J2.10 J2.12 J2.13 J2.14 J3.11 J3.12 LBL1.0 SH-J1.0 SH-J2.0 SH-J3.0 SH-J4.0 SH-J5.0 SH-J6.0 SH-J7.0 SH-J8.0 SH-J9.0 SH-J10.0 SH-J11.0 SH-J12.0 SH-J13.0 SH-J14.0 SH-J15.0 SH-J16.0 SH-J17.0 SH-J18.0 SH-J19.0 SH-J20.0 U1.3 U1.4 U1.5 U1.6 U1.7 U1.8 U1.10 U1.12 U1.13 U1.18 U1.19 U1.22 U1.23 U1.24 U1.25 U1.26 U1.27 U1.28 U1.29 U1.30 U1.31 U1.32 U1.33 U1.34 U1.35 U1.36 U1.41 U1.42 U1.45 U1.46 U1.47 U1.48 U3.7@7.587,17.545 U3.7@8.487,17.545 U4.4

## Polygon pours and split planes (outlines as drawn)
GND on Top Layer "TOP_LAYER_GND_P116" (solid, remove dead copper, pour order 116): 0,0 85.344,0 85.344,62.941 0,62.941
BOUT2 on Top Layer "TOP_LAYER_BOUT2_P114" (solid, remove dead copper, pour order 114): 64.612,36.728 64.16,36.277 64.16,35.78 71.933,35.78 71.933,38.92 81.915,38.92 81.915,46.035 77.343,46.035 77.343,40.849 70.51,40.849 70.51,36.728
AISEN on Top Layer "TOP_LAYER_AISEN_P112" (solid, remove dead copper, pour order 112): 72.39,35.357 72.39,32.614 76.657,32.614 76.657,35.357
BISEN on Top Layer "TOP_LAYER_BISEN_P104" (solid, remove dead copper, pour order 104): 72.39,35.814 72.39,38.71 76.657,38.71 76.657,35.814
AOUT2 on Top Layer "TOP_LAYER_AOUT2_P100" (solid, remove dead copper, pour order 100): 64.612,34.448 64.16,34.9 64.16,35.367 64.465,35.367 71.933,35.367 71.933,32.256 81.915,32.256 81.915,25.141 77.343,25.141 77.343,30.327 70.51,30.327 70.51,34.448
BOUT1 on Top Layer "TOP_LAYER_BOUT1_P098" (solid, remove dead copper, pour order 98): 63.432,41.453 63.246,41.266 63.246,37.62 62.2,37.62 62.2,42.241 62.631,42.672 73.152,42.672 73.152,52.92 80.924,52.925 80.924,46.792 76.657,46.792 76.657,41.453
AOUT1 on Top Layer "TOP_LAYER_AOUT1_P088" (solid, remove dead copper, pour order 88): 63.59,29.566 63.246,29.91 63.246,33.528 62.2,33.528 62.2,28.935 62.789,28.346 73.152,28.346 73.152,17.989 80.924,17.983 80.924,24.384 76.657,24.384 76.657,29.566
VM on Top Layer "TOP_LAYER_VM_P070" (solid, remove dead copper, pour order 70): 51.75,0 51.75,38 50.071,38 50.071,20.25 47.449,20.25 47.449,6.25 39.53,6.25 39.5,6.28 39.5,0
EZFET_USB_Shield on Top Layer "TOP_LAYER_EZFET_USB_SHIELD_P000" (solid, remove dead copper, pour order 0): 5.949,18.13 -0.045,18.13 -0.045,29.596 5.949,29.596
VCC on Signal Layer 2 "Signal Layer 2-VCC" (solid, pour order 121): 0,37.5 26,37.5 25.967,37.533 25.967,37.636 26.378,37.636 26.378,35.074 33.088,35.074 32.932,62.941 0,62.941
GND on Signal Layer 2 "SIGNAL_LAYER_2_GND_P118" (solid, remove dead copper, pour order 118): 0,0 85.344,0 85.344,62.941 0,62.941
EZFET_VCC on Signal Layer 2 "SIGNAL_LAYER_2_EZFET_VCC_P006" (solid, remove dead copper, pour order 6): 0,12.5 37.05,12.5 37.05,26.63 37,26.58 26,26.58 26,37.25 0,37.25
EZFET_VBUS on Signal Layer 2 "SIGNAL_LAYER_2_EZFET_VBUS_P004" (solid, remove dead copper, pour order 4): -0.045,18.13 9.75,18.13 9.75,29.596 -0.045,29.596
GND on Bottom Layer "BOTTOM_LAYER_GND_P119" (solid, remove dead copper, pour order 119): 0,0 85.344,0 85.344,62.941 0,62.941
BISEN on Bottom Layer "BOTTOM_LAYER_BISEN_P110" (solid, remove dead copper, pour order 110): 69.952,38.71 76.657,38.71 76.657,35.814 63.703,35.814 63.703,40.849 69.952,40.849
AISEN on Bottom Layer "BOTTOM_LAYER_AISEN_P106" (solid, remove dead copper, pour order 106): 69.952,32.614 76.657,32.614 76.657,35.367 76.647,35.357 63.703,35.357 63.703,30.25 69.952,30.25
EZFET_USB_Shield on Bottom Layer "BOTTOM_LAYER_EZFET_USB_SHIELD_P010" (solid, remove dead copper, pour order 10): 5.949,18.125 -0.045,18.125 -0.045,29.591 5.949,29.591
GND on Signal Layer 1 "SIGNAL_LAYER_1_GND_P117" (solid, remove dead copper, pour order 117): 0,0 85.344,0 85.344,62.941 0,62.941

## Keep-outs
Keep-Out Layer:
  text ".Layer_Name" at 14.656,-21.806 h1.52

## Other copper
Top Layer:
  region net GND: 21.271,21.352 23.987,21.352 23.987,21.147 21.271,21.14
  region net BOUT2: 64.049,36.096 64.16,36.207 64.16,36.096 64.16,35.78 60.275,35.78 60.275,36.096
  region net AISEN: 70.025,33.931 64.573,33.931 63.753,34.75 60.325,34.75 60.325,34.419 63.068,34.419 63.753,33.734 63.753,30.25 70.025,30.25
  region net BOUT1: 60.275,37.374 61.954,37.374 62.2,37.62 63.246,37.62 63.246,37.315 62.941,37.01 60.275,37.01
  region net AOUT1: 60.275,33.774 61.954,33.774 62.2,33.528 63.246,33.528 63.246,33.833 62.941,34.138 60.275,34.138
  region net AOUT2: 64.008,35.052 64.16,34.9 64.16,35.052 64.16,35.367 60.275,35.367 60.275,35.052
  region net BISEN: 70.025,37.169 64.573,37.169 63.753,36.349 60.325,36.349 60.325,36.681 63.068,36.681 63.753,37.366 63.753,40.849 70.025,40.849
  text ".Layer_Name" at 14.656,-21.806 h1.52
Bottom Layer:
  text ".Layer_Name" at 14.656,-21.806 h1.52

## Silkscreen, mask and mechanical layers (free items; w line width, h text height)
Top Overlay:
  lines w0.152: 11.099,19.13 8.893,19.13 8.893,22.404 11.099,22.404 11.099,18.856 11.465,18.49 11.465,16.018 12.487,14.996 12.497,13.185 ; 10.095,8.5 10.095,13.185 13.5,13.185 13.5,8.5 10.095,8.5
  lines w0.254: 2.037,6.09 2.037,8 3.845,8 ; 2.845,57.686 2.845,58.292 ; 7.925,57.519 7.925,58.129 ; 19.275,43.577 19.275,44.294 19.479,44.497 ; 22.063,43.6 22.467,43.196 22.467,43.196 ; 48.463,26.06 68.885,26.06 68.885,44.806 48.463,44.806 48.463,26.06 ; 51.304,50.255 64.75,50.255 64.75,59.245 51.304,59.245 51.304,50.255
  text "AIN1" at 40.662,59.131 h1.02
  text "RST" at 1.575,56.38 h1.02
  text "PUSH" at 5.385,56.353 h1.02
  text "GND" at 70.31,56.101 h1.85
  text "AIN2" at 40.662,55.474 h1.02
  text "GUI" at 59.596,54.705 h1.02
  text "MCU" at 52.353,54.55 h1.02
  text "BIN1" at 40.662,52.154 h1.02
  text "STALL" at 51.945,51 h1.02
  text "nFAULT" at 58,50.734 h1.02
  text "BIN2" at 40.662,48.92 h1.02
  text "STATUS LEDs" at 52.578,48.158 h1.02
  text "BOUT1" at 84.43,46.939 h1.02 r90
  text "nFAULT" at 40.662,45.415 h1.02
  text "DRV8410/11" at 53.188,43.031 h1.02
  text "nSLEEP" at 40.662,41.91 h1.02
  text "BOUT2" at 84.43,41.3 h1.02 r90
  text "TST" at 5.639,40.181 h1.02 r90
  text "RST" at 8.202,40.181 h1.02 r90
  text "TX" at 10.79,40.181 h1.02 r90
  text "RX" at 13.321,40.181 h1.02 r90
  text "3V3" at 15.85,40.181 h1.02 r90
  text "GND" at 20.895,40.181 h1.02 r90
  text "VSEN_A" at 40.662,38.557 h1.02
  text "VSEN_B" at 40.662,35.129 h1.02
  text "VCC" at 40.662,31.699 h1.02
  text "GND" at 40.662,28.194 h1.02
  text "AOUT2" at 84.277,25.451 h1.02 r90
  text "AOUT1" at 84.277,19.977 h1.02 r90
  text "'.PRJ_Number'.PCB_Rev" at 63.246,12.344 h2.75
  text "VM" at 40.386,6.706 h1.02
  text "GND" at 66.142,4.115 h1.02
  text "VM" at 48.616,0.914 h1.02
  text "GND" at 53.645,0.914 h1.02
  text ".Layer_Name" at 14.656,-21.806 h1.52
Bottom Overlay:
  text ".Layer_Name" at 14.656,-21.806 h1.52
Top Paste:
  text ".Layer_Name" at 14.656,-21.806 h1.52
Bottom Paste:
  text ".Layer_Name" at 14.656,-21.806 h1.52
Top Solder:
  text ".Layer_Name" at 14.656,-21.806 h1.52
  text ".Layer_Name" at 14.656,-21.806 h1.52
Bottom Solder:
  text ".Layer_Name" at 14.656,-21.806 h1.52
Drill Guide:
  text ".Layer_Name" at 14.656,-21.806 h1.52
M1 Board Outline:
  the board outline again, w0.254
  text ".Layer_Name" at 14.656,-21.806 h1.52
M2 Board Dimensions:
  rectangle: 0,-6.985 3.175,-3.81
  rectangle: 3.175,-10.16 12.7,-6.985
  lines w0.178: 0,-6.985 25.4,-6.985 ; 3.175,-10.16 3.175,-3.81 ; 6.35,-10.16 6.35,-3.81 ; 12.7,-10.16 12.7,-3.81 ; 19.05,-10.16 19.05,-3.81 ; 0,-10.16 25.4,-10.16 25.4,-3.81 0,-3.81 0,-10.16
  text ".Layer_Name" at 14.656,-21.806 h1.52
M3 3D STEP Top:
  text ".Layer_Name" at 14.656,-21.806 h1.52
M4 3D STEP Bottom:
  text ".Layer_Name" at 14.656,-21.806 h1.52
M5 Assembly Top:
  lines w0.254: -7.417,-23.626 160.223,-23.626 ; -7.417,-18.462 160.274,-18.462 ; -7.417,-13.297 -7.417,-28.791 94.31,-28.791 160.274,-28.791 160.274,-13.297 -7.404,-13.297 -7.404,-28.791 32.614,-28.791 ; 55.194,-28.791 55.194,-13.297 ; 87.376,-18.462 87.376,-13.297 ; 108.712,-18.462 108.712,-13.297 ; 124.511,-28.956 124.511,-23.804
  text "COMPONENTS MARKED 'DNP' SHOULD NOT BE POPULATED." at 29.299,-8.09 h1.52
  text "ASSEMBLY VARIANT:" at 29.286,-11.024 h1.52
  text ".VariantName" at 55.601,-11.024 h1.52
  text "PCB VIEWED FROM TOP SIDE" at -5.804,-16.654 h1.52
  text "BOARD #:" at 57.099,-16.654 h1.52
  text ".PRJ_Number" at 70.955,-16.654 h1.52
  text "REV:" at 92.405,-16.654 h1.52
  text ".PCB_Rev" at 99.809,-16.654 h1.52
  text "SVN REV:" at 113.69,-16.654 h1.52
  text ".VersionControl_RevNumber" at 126.543,-16.654 h1.52
  text "TID #:" at 57.099,-21.819 h1.52
  text ".TID" at 70.955,-21.819 h1.52
  text "PLOT NAME =" at -5.804,-27.034 h1.52
  text ".plot_File_Name" at 14.656,-27.034 h1.52
  text "GENERATED    :" at 57.15,-27.034 h1.52
  text ".Print_Date" at 79.235,-27.034 h1.52
  text ".Print_Time" at 97.752,-27.034 h1.52
  text "TEXAS INSTRUMENTS" at 129.87,-27.034 h1.52
M6 Assembly Bottom:
  lines w0.254: -7.429,-18.474 160.261,-18.474 ; -7.379,-23.639 160.261,-23.639 ; 28.334,-28.969 28.334,-23.817 ; 44.133,-18.474 44.133,-13.31 ; 65.468,-18.474 65.468,-13.31 ; 97.65,-28.804 97.65,-13.31 ; 120.231,-28.804 160.249,-28.804 160.249,-13.31 -7.429,-13.31 -7.429,-28.804 58.534,-28.804 160.261,-28.804 160.261,-13.31
  text "COMPONENTS MARKED 'DNP' SHOULD NOT BE POPULATED." at 154.991,-8.077 h1.52
  text ".VariantName" at 128.473,-11.024 h1.52
  text "ASSEMBLY VARIANT:" at 154.864,-11.024 h1.52
  text ".VersionControl_RevNumber" at 26.302,-16.667 h1.52
  text "SVN REV:" at 39.154,-16.667 h1.52
  text ".PCB_Rev" at 53.035,-16.667 h1.52
  text "REV:" at 60.439,-16.667 h1.52
  text ".PRJ_Number" at 81.89,-16.667 h1.52
  text "BOARD #:" at 95.745,-16.667 h1.52
  text "PCB VIEWED FROM BOTTOM SIDE" at 158.648,-16.667 h1.52
  text ".TID" at 81.89,-21.831 h1.52
  text "TID #:" at 95.745,-21.831 h1.52
  text "TEXAS INSTRUMENTS" at 22.974,-27.047 h1.52
  text ".Print_Time" at 55.093,-27.047 h1.52
  text ".Print_Date" at 73.609,-27.047 h1.52
  text "GENERATED    :" at 95.694,-27.047 h1.52
  text ".plot_File_Name" at 138.189,-27.047 h1.52
  text "PLOT NAME =" at 158.648,-27.047 h1.52
M9 Title Sheet:
  drawing of 57 lines, arcs and shapes, not listed
  text "1" at 18.792,204.127 h1.78
  text "2" at 82.182,204.127 h1.78
  text "3" at 145.411,204.127 h1.78
  text "4" at 209.08,204.127 h1.78
  text "5" at 272.555,204.127 h1.78
  text "6" at 336.182,204.127 h1.78
  text "A" at -10.579,175.095 h1.78
  text "A" at 365.341,175.095 h1.78
  text "B" at -10.579,114.643 h1.78
  text "B" at 365.341,114.643 h1.78
  text "C" at -10.579,54.318 h1.78
  text "C" at 365.341,54.318 h1.78
  text "PROJECT TITLE:" at 288.125,7.048 h1.14
  text ".PRJ_Title" at 289.395,3.662 h1.78
  text "DESIGNED FOR:" at 288.125,-0.597 h1.14
  text ".PRJ_Customer" at 289.395,-4.153 h1.78
  text "D" at -10.579,-5.88 h1.78
  text "D" at 365.341,-5.88 h1.78
  text "FILE NAME:" at 288.125,-8.217 h1.14
  text ".PCB_File_Name_No_Path" at 289.395,-11.265 h1.78
  text "Texas Instruments (TI) and/or its licensors do not warrant the accuracy or completeness of this specification" at 161.9,-15.376 h1.14
  text "ENGINEER:" at 288.125,-15.583 h1.14
  text "LAYOUT BY:" at 326.352,-15.583 h1.14
  text "or any information contained therein. TI and/or its licensors do not warrant that this design will meet" at 160.757,-18.237 h1.14
  text ".PRJ_Engineer" at 289.395,-19.52 h1.78
  text ".PCB_Layout" at 327.635,-19.52 h1.78
  text "the specifications, will be suitable for your application or fit for any particular purpose, or will operate in" at 160.757,-21.099 h1.14
  text ".Layer_Name" at 14.656,-21.806 h1.52
  text "ALTIUM DESIGNER VERSION:" at 326.352,-23.457 h1.14
  text "an implementation. TI and/or its licensors do not warrant that the design is production worthy. You should" at 160.757,-23.961 h1.14
  text "completely validate and test your design implementation to confirm the system functionality for your application." at 161.9,-26.822 h1.14
  text ".print_Scale" at 289.395,-26.843 h1.78
  text ".Application_BuildNumber" at 327.635,-26.843 h1.78
  text "1" at 18.792,-32.093 h1.78
  text "2" at 82.182,-32.093 h1.78
  text "3" at 145.411,-32.093 h1.78
  text "4" at 209.08,-32.093 h1.78
  text "5" at 272.555,-32.093 h1.78
  text "6" at 336.182,-32.093 h1.78
M10 Fab Notes:
  drawing of 189 lines, arcs and shapes, not listed
  text "DESIGN INFORMATION" at 314.503,161.447 h1.52
  text "MIN. TRACK WIDTH:" at 298.131,158.091 h1.52
  text "8" at 325.976,158.091 h1.52
  text "MIL" at 329.907,158.091 h1.52
  text "MIN. CLEARANCE:" at 298.131,154.938 h1.52
  text "0.2" at 324.452,154.938 h1.52
  text "mm" at 329.907,154.938 h1.52
  text "MIN. VIA PAD SIZE:" at 298.131,151.785 h1.52
  text "24" at 325.214,151.785 h1.52
  text "MIL" at 329.907,151.785 h1.52
  text "0.05mm (2MIL)" at 315.784,148.486 h1.52
  text "MINIMUM ANNULAR RING" at 289.769,148.277 h1.52
  text "EXTERNAL" at 333.768,148.277 h1.52
  text "PER" at 294.849,145.48 h1.52
  text "IPC-D-275 CLASS 2 LEVEL C" at 300.437,145.48 h1.52
  text "MIL, HOLES" at 338.238,142.928 h1.52
  text "+/-" at 328.27,142.709 h1.52
  text "+/-" at 349.961,142.709 h1.52
  text "REGISTRATION TOLERANCES:" at 289.769,142.682 h1.52
  text "METAL" at 320.243,142.682 h1.52
  text "5" at 334.879,142.683 h1.52
  text "3" at 356.037,142.683 h1.52
  text "MIL" at 358.99,142.682 h1.52
  text "HOLE SIZE TOLERANCE (UNLESS OTHERWISE SPECIFIED):" at 289.769,140.185 h1.52
  text "+/-" at 349.961,140.112 h1.52
  text "3" at 356.037,140.085 h1.52
  text "MIL" at 358.99,140.085 h1.52
  text "MATERIAL:" at 287.87,136.589 h1.52
  text "FR-4 High Tg" at 312.926,133.324 h1.52
  text "X" at 309.257,133.122 h1.52
  text "FR-408" at 298.563,133.007 h1.52
  text "OTHER" at 336.358,133.007 h1.52
  text "62 MIL (1.6mm) +/-10%" at 306.694,129.374 h1.52
  text "X" at 303.643,129.312 h1.52
  text "THICKNESS:" at 289.769,129.165 h1.52
  text "OTHER" at 339.33,129.165 h1.52
  text "TOLERANCE:" at 289.769,125.652 h1.52
  text "X" at 311.314,125.652 h1.52
  text "ANSI IPC-6012 TYPE 3 CLASS 2" at 315.836,125.652 h1.52
  text "OTHER +/-" at 315.835,121.989 h1.52
  text "BOW & TWIST:" at 289.769,118.302 h1.52
  text "X" at 311.314,118.302 h1.52
  text "ANSI IPC-6012 TYPE 3 CLASS 2" at 315.836,118.302 h1.52
  text "OTHER +/-" at 315.835,114.576 h1.52
  text "DRILLING:" at 287.87,111.258 h1.52
  text "NC_DRILL FILES" at 332.599,108.586 h1.52
  text "REFERENCE:" at 289.769,108.486 h1.52
  text "X" at 306.463,108.484 h1.52
  text "AS SHOWN" at 310.984,108.486 h1.52
  text "X" at 329.348,108.486 h1.52
  text "OTHER" at 340.168,104.873 h1.52
  text "PTH COPPER THICKNESS:" at 289.761,104.783 h1.52
  text "X" at 318.697,104.783 h1.52
  text "20-30 um" at 321.948,104.783 h1.52
  text "BOARD FINISH:" at 287.87,101.034 h1.52
  text "SILKSCREEN:" at 291.812,98.237 h1.52
  text "X" at 316.14,98.237 h1.52
  text "TOP" at 319.112,98.237 h1.52
  text "X" at 329.094,98.237 h1.52
  text "BOTTOM" at 332.091,98.237 h1.52
  text "SILKSCREEN COLOR:" at 291.812,94.295 h1.52
  text "X" at 316.115,94.295 h1.52
  text "WHITE" at 319.112,94.295 h1.52
  text "OTHER" at 332.091,94.295 h1.52
  text "X" at 319.442,90.652 h1.52
  text "GREEN" at 322.439,90.652 h1.52
  text "OTHER" at 338.136,90.652 h1.52
  text "SOLDER RESIST COLOR:" at 291.812,90.477 h1.52
  text "X" at 319.442,86.734 h1.52
  text "MATTE" at 322.439,86.734 h1.52
  text "SEMI-GLOSS" at 338.125,86.717 h1.52
  text "IMMERSION GOLD (ENIG)" at 314.819,82.345 h1.52
  text "ENEPIG" at 348.793,82.162 h1.52
  text "SURFACE FINISH:" at 287.87,82.136 h1.52
  text "X" at 310.298,82.136 h1.52
  text "IMM. TIN/SILVER OR EQUIV" at 296.24,78.649 h1.52
  text "OTHER" at 332.599,78.549 h1.52
  text "ARRAY/PANEL:" at 287.87,74.602 h1.52
  text "CUT AND TRIM PER M1 BOARD OUTLINE" at 314.819,74.393 h1.52
  text "N.C. ROUTE" at 314.819,70.94 h1.52
  text "X" at 332.295,70.94 h1.52
  text "V. SCORE" at 336.816,70.94 h1.52
  text "CERTIFICATION:" at 287.87,67.66 h1.52
  text "MATERIALS AND WORKMANSHIP FOR ALL PCBS" at 306.285,67.66 h1.52
  text "TO MEET OR EXCEED THE REQUIREMENTS OF:" at 306.285,65.271 h1.52
  text "X" at 297.078,62.003 h1.52
  text "ANSI IPC-A-600F CLASS ->" at 300.329,62.003 h1.52
  text "X" at 342.188,62.003 h1.52
  text "2" at 344.982,62.003 h1.52
  text "1" at 336.981,61.965 h1.52
  text "3" at 353.973,61.965 h1.52
  text "X" at 317.702,58.252 h1.52
  text "RoHS" at 320.953,58.252 h1.52
  text "OTHER" at 337.321,58.252 h1.52
  text "PER ORDER" at 347.407,58.252 h1.52
  text "ALL BOARDS MUST MEET OR EXCEED UL94-V0 REQUIREMENTS." at 288.569,54.345 h1.52
  text "PCB MUST BEAR THE UL94V-0 UL REGISTERED MATERIAL ID NUMBER" at 288.569,51.397 h1.52
  text "ADDITIONAL REQUIREMENTS:" at 287.87,47.094 h1.52
  text "MICROSECTION:" at 289.769,44.373 h1.52
  text "YES" at 312.775,44.373 h1.52
  text "REQUIRED" at 334.657,40.707 h1.52
  text "BARE BOARD ELEC. TEST:" at 289.769,40.634 h1.52
  text "NONE" at 322.935,40.634 h1.52
  text "X" at 331.66,40.634 h1.52
  text "PER ORDER" at 349.693,40.634 h1.52
  text "XX MIL VIAS REQUIRE NON-CONDUCTIVE FILL AND PLANARIZE" at 294.04,35.428 h1.5
  text "XX MIL VIAS REQUIRE CONDUCTIVE FILL AND PLANARIZE" at 294.243,32.787 h1.52
  text "OUTER XX MIL TRACES REQUIRE 50 OHM SINGLE-ENDED IMPEDANCE" at 294.218,28.637 h1.47
  text "LAYER 2 & 3 (INNER LAYERS) XX MIL WIDE, XX MIL SPACE / TRACES REQUIRE 100 OHM DIFFERENTIAL IMPEDANCE" at 294.015,22.65 h1.52
  text ".Layer_Name" at 14.656,-21.806 h1.52
M11 Gerber Information:
  lines w0.254: -7.417,-23.626 160.223,-23.626 ; -7.417,-18.462 160.274,-18.462 ; -7.417,-13.297 -7.417,-28.791 94.31,-28.791 160.274,-28.791 160.274,-13.297 -7.404,-13.297 -7.404,-28.791 32.614,-28.791 ; 55.194,-28.791 55.194,-13.297 ; 87.376,-18.462 87.376,-13.297 ; 108.712,-18.462 108.712,-13.297 ; 124.511,-28.956 124.511,-23.804
  text "ALL ARTWORK VIEWED FROM TOP SIDE" at -5.804,-16.654 h1.52
  text "BOARD #:" at 57.099,-16.654 h1.52
  text ".PRJ_Number" at 70.955,-16.654 h1.52
  text "REV:" at 92.405,-16.654 h1.52
  text ".PCB_Rev" at 99.809,-16.654 h1.52
  text "SVN REV:" at 113.69,-16.654 h1.52
  text ".VersionControl_RevNumber" at 126.543,-16.654 h1.52
  text "LAYER NAME =" at -5.804,-21.806 h1.52
  text "TID #:" at 57.099,-21.819 h1.52
  text ".TID" at 70.955,-21.819 h1.52
  text "PLOT NAME =" at -5.804,-27.034 h1.52
  text ".plot_File_Name" at 14.656,-27.034 h1.52
  text "GENERATED    :" at 57.15,-27.034 h1.52
  text ".Print_Date" at 79.235,-27.034 h1.52
  text ".Print_Time" at 97.752,-27.034 h1.52
  text "TEXAS INSTRUMENTS" at 129.87,-27.034 h1.52
M12 Stackup:
  drawing of 295 lines, arcs and shapes, not listed
  text "Layer" at 249.469,197.166 h1.52
  text "Name" at 259.88,197.166 h1.52
  text "Material" at 283.75,197.166 h1.52
  text "Thickness" at 305.588,197.166 h1.52
  text "Constant" at 322.094,197.166 h1.52
  text "Board Layer Stack" at 336.568,197.166 h1.52
  text "Top Overlay" at 259.88,194.118 h1.52
  text "Top Solder" at 259.88,191.07 h1.52
  text "Solder Resist" at 283.75,191.07 h1.52
  text "0.40mil" at 305.588,191.07 h1.52
  text "3.5" at 322.094,191.07 h1.52
  text "1" at 249.469,188.022 h1.52
  text "Top Layer" at 259.88,188.022 h1.52
  text "2.80mil" at 305.588,188.022 h1.52
  text "Dielectric 1" at 259.88,184.974 h1.52
  text "FR-4" at 283.75,184.974 h1.52
  text "8.00mil" at 305.588,184.974 h1.52
  text "4.2" at 322.094,184.974 h1.52
  text "2" at 249.469,181.926 h1.52
  text "Signal Layer 1" at 259.88,181.926 h1.52
  text "1.40mil" at 305.588,181.926 h1.52
  text "Dielectric 2" at 259.88,178.878 h1.52
  text "FR-4" at 283.75,178.878 h1.52
  text "37.20mil" at 305.588,178.878 h1.52
  text "4.2" at 322.094,178.878 h1.52
  text "3" at 249.469,175.83 h1.52
  text "Signal Layer 2" at 259.88,175.83 h1.52
  text "1.40mil" at 305.588,175.83 h1.52
  text "Dielectric 3" at 259.88,172.782 h1.52
  text "FR-4" at 283.75,172.782 h1.52
  text "8.00mil" at 305.588,172.782 h1.52
  text "4.2" at 322.094,172.782 h1.52
  text "4" at 249.469,169.734 h1.52
  text "Bottom Layer" at 259.88,169.734 h1.52
  text "2.80mil" at 305.588,169.734 h1.52
  text "Bottom Solder" at 259.88,166.686 h1.52
  text "Solder Resist" at 283.75,166.686 h1.52
  text "0.40mil" at 305.588,166.686 h1.52
  text "3.5" at 322.094,166.686 h1.52
  text "Bottom Overlay" at 259.88,163.638 h1.52
  text ".Layer_Name" at 14.656,-21.806 h1.52
M13 Component Bodies Top:
  text ".Layer_Name" at 14.656,-21.806 h1.52
M14 Component Bodies Bottom:
  text ".Layer_Name" at 14.656,-21.806 h1.52
M15 Courtyards Top:
  text ".Layer_Name" at 14.656,-21.806 h1.52
M16 Courtyards Bottom:
  text ".Layer_Name" at 14.656,-21.806 h1.52
Drill Drawing:
  circle w0.254: c136.238,81.313 r0.421
  circle w0.254: c136.238,81.313 r0.702
  lines w0.254: 135.537,64.822 136.94,64.822 136.94,66.226 135.537,66.226 135.537,64.822 ; 135.537,69.383 136.94,69.383 136.238,67.98 135.537,69.383 ; 135.537,71.138 135.537,71.489 135.888,71.839 135.537,72.19 135.537,72.541 135.888,72.541 136.238,72.19 136.589,72.541 136.94,72.541 136.94,72.19 136.589,71.839 136.94,71.489 136.94,71.138 136.589,71.138 136.238,71.489 135.888,71.138 135.537,71.138 ; 135.537,74.646 135.888,74.646 136.238,74.295 136.589,74.646 136.94,74.646 136.589,74.997 136.94,75.348 136.589,75.348 136.238,75.699 135.888,75.348 135.537,75.348 135.888,74.997 135.537,74.646 ; 135.537,77.804 135.888,77.804 135.888,77.453 136.589,77.453 136.589,77.804 136.94,77.804 136.94,78.506 136.589,78.506 136.589,78.857 135.888,78.857 135.888,78.506 135.537,78.506 135.537,77.804 ; 135.537,83.769 136.238,84.12 136.94,83.769 136.589,84.47 136.94,85.172 136.238,84.821 135.537,85.172 135.888,84.47 135.537,83.769
  lines w0.305: 134.264,63.875 216.344,63.875 ; 134.264,85.979 216.344,85.979 ; 142.846,60.717 142.846,89.137 ; 151.279,60.717 151.279,89.137 ; 167.448,60.717 167.448,89.137 ; 174.03,60.717 174.03,89.137 ; 183.559,60.717 183.559,89.137 ; 201.957,60.717 201.957,89.137 ; 134.264,60.717 216.344,60.717 216.344,89.137 134.264,89.137 134.264,60.717
  text "Symbol" at 136.159,86.926 h1.83
  text "Quantity" at 143.793,86.926 h1.83
  text "Finished Hole Size" at 152.226,86.926 h1.83
  text "Plated" at 168.395,86.926 h1.83
  text "Hole Type" at 174.977,86.926 h1.83
  text "Drill Layer Pair" at 184.506,86.926 h1.83
  text "Hole Tolerance" at 202.904,86.926 h1.83
  text "2" at 143.793,83.769 h1.52
  text "27.56mil (0.700mm)" at 152.226,83.769 h1.52
  text "NPTH" at 168.395,83.769 h1.52
  text "Round" at 174.977,83.769 h1.52
  text "Top Layer - Bottom Layer" at 184.506,83.769 h1.52
  text "231" at 143.793,80.611 h1.52
  text "12.00mil (0.305mm)" at 152.226,80.611 h1.52
  text "PTH" at 168.395,80.611 h1.52
  text "Round" at 174.977,80.611 h1.52
  text "Top Layer - Bottom Layer" at 184.506,80.611 h1.52
  text "9" at 143.793,77.453 h1.52
  text "17.72mil (0.450mm)" at 152.226,77.453 h1.52
  text "PTH" at 168.395,77.453 h1.52
  text "Round" at 174.977,77.453 h1.52
  text "Top Layer - Bottom Layer" at 184.506,77.453 h1.52
  text "30" at 143.793,74.295 h1.52
  text "40.00mil (1.016mm)" at 152.226,74.295 h1.52
  text "PTH" at 168.395,74.295 h1.52
  text "Round" at 174.977,74.295 h1.52
  text "Top Layer - Bottom Layer" at 184.506,74.295 h1.52
  text "28" at 143.793,71.138 h1.52
  text "43.31mil (1.100mm)" at 152.226,71.138 h1.52
  text "PTH" at 168.395,71.138 h1.52
  text "Round" at 174.977,71.138 h1.52
  text "Top Layer - Bottom Layer" at 184.506,71.138 h1.52
  text "+/-1.97mil" at 202.904,71.138 h1.52
  text "5" at 143.793,67.98 h1.52
  text "45.28mil (1.150mm)" at 152.226,67.98 h1.52
  text "PTH" at 168.395,67.98 h1.52
  text "Round" at 174.977,67.98 h1.52
  text "Top Layer - Bottom Layer" at 184.506,67.98 h1.52
  text "10" at 143.793,64.822 h1.52
  text "51.18mil (1.300mm)" at 152.226,64.822 h1.52
  text "PTH" at 168.395,64.822 h1.52
  text "Round" at 174.977,64.822 h1.52
  text "Top Layer - Bottom Layer" at 184.506,64.822 h1.52
  text "315 Total" at 143.793,61.665 h1.52
  text ".Layer_Name" at 14.656,-21.806 h1.52
Mechanical 17:
  text ".Layer_Name" at 14.656,-21.806 h1.52
Mechanical 18:
  text ".Layer_Name" at 14.656,-21.806 h1.52
Mechanical 19:
  text ".Layer_Name" at 14.656,-21.806 h1.52

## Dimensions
0,-10.16 to 25.4,-10.16 on M2 Board Dimensions
0,0 to 0,64.008 on M2 Board Dimensions
0,0 to 85.344,0 on M2 Board Dimensions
